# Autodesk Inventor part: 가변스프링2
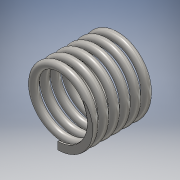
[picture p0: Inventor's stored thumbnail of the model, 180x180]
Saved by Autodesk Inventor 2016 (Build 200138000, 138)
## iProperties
Created: 2021-02
Part Number: 가변스프링2
Material: 강철, 탄소
Document SubType Name: Modeling
Designer: Windows7
Density: 7.85 g/cm^3
Appearance: 반연마
Mass: 7.71138 g
Surface Area: 20.0174 cm^2
Volume: 0.982341 cm^3
Author: Windows7
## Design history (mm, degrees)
sketch "스케치1"
  geometry: L1 (0, 0)-(17, 0); L2 (17, 0)-(17, -8.5); L3 (17, -8.5)-(0, -8.5); L4 (0, -8.5)-(0, 0); C1 r 1 at (17, -8.5)
  constraints: 8 end point, 2 parallel, 1 centre point, 1 coincident, 1 horizontal, 1 perpendicular
  dimensions: "d0" = 17 distance between parallel lines of L4 L2 (derived); "d1" = 17 diameter of L3 L1; "d2" = 2 diameter of C1
feature "코일1" sketch "스케치1" pitch "d3" = 10; turns "d5" = 6; dims "d4" = 17 (= d0), "d6" = 0, angle "d7" = 90 deg, angle "d8" = 90 deg, "d9" = 0, "d10" = 0
sketch "스케치2"
  geometry: L1 (0, -7.5)-(0, -9.5) reference; 1 further point
  constraints: 1 vertical alignment
extrude "돌출1" cut sketch "스케치2" distance "d11" = 10; taper "d12" = 0 deg
node "작업 평면1"
sketch "스케치3"
  geometry: L1 (7.5, 0)-(9.5, 0) reference; 2 further points
  constraints: 2 other
extrude "돌출2" cut sketch "스케치3" distance "d14" = 10; taper "d15" = 0 deg
node "솔리드1"
node "절단 모서리 투영1"
node "절단 모서리 투영2"
other parameters: "d13" = 90 deg
